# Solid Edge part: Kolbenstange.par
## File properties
Username: ahadarics
Dokumentum tartalom típus: 0
Author: ahadarics
Last saved by: ahadarics
Revision: 84
Sűrűség: 0,000 kg/m^3
Pontosság: 0,990
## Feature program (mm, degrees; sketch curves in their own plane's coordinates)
base feature "unnamed BaseFeature 1"
thread "unnamed Thread 1"
sketch for "Kihúzás_1" plane through (59.75, 0, 0) normal (1, 0, 0) x-axis (0, -1, 0)
  circle centre (0, 0) radius 10
extrude "Kihúzás_1" add finite 32 along -normal
chamfer "Letörés_1" setback 0.4
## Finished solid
Body 1: solid body, 13 faces, 23 edges, 12 vertices.
  Faces by surface: plane 9, cylinder 3, cone 1
  Edges by curve: line 12, circle 11
Bounding box of the edges (mm): 343.500 x 20.000 x 20.000, from (-283.75, -10, -10) to (59.75, 10, 10).
Cylindrical faces by radius (mm): R4 x2, R10 x1
Conical faces (half-angle, radius in mm at the cone's reference point): 45 deg R3.6 x1
Planar faces by outward normal: +x 3, +z 1, -x 4, -z 1
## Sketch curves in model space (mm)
circle centre (59.75, 0, 0) radius 10
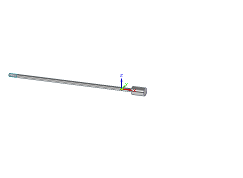
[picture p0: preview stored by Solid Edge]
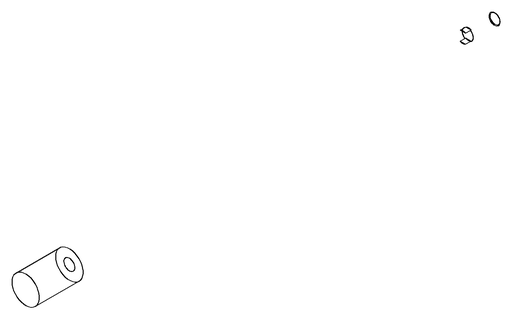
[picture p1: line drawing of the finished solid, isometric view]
